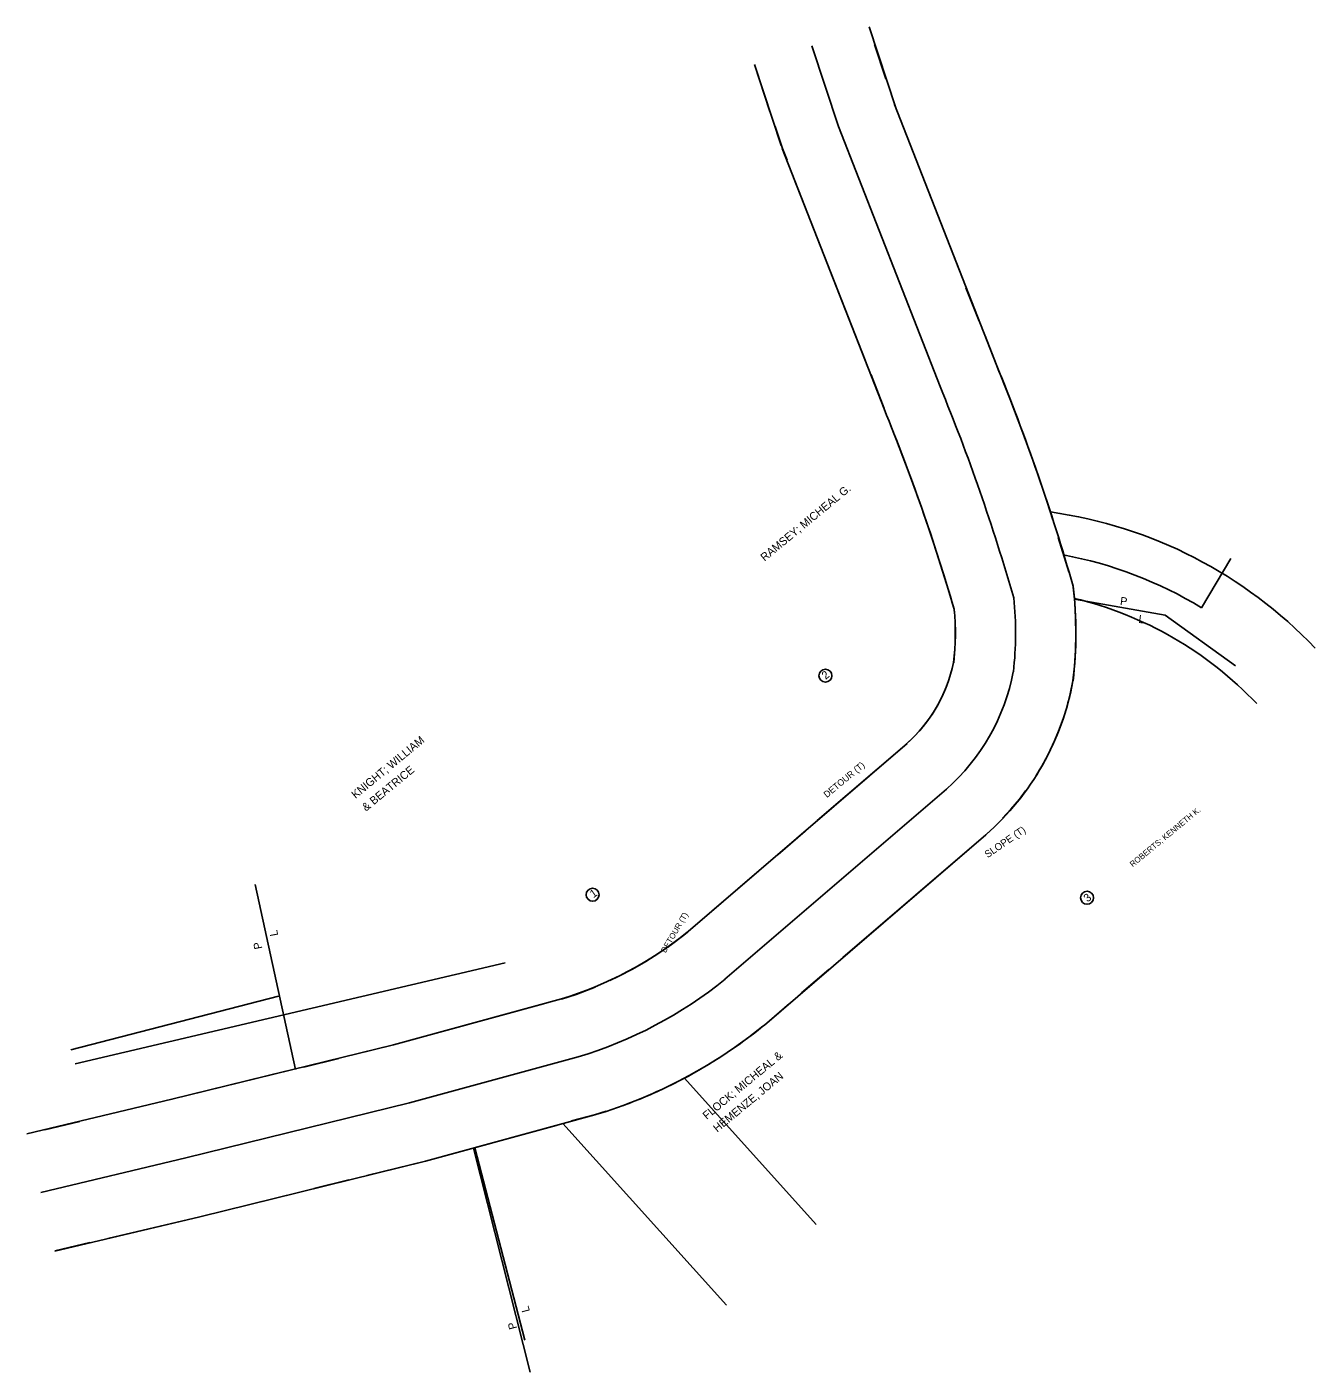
# Model space of a CAD drawing. Extents: x 461210 to 461371, y 202911 to 203079.
import ezdxf

# ---------------------------------------------------------------- set-up
doc = ezdxf.new("R2010")
doc.units = 0
for name, color, linetype in [('Level 1', 7, 'Continuous'), ('Level 3', 7, 'Continuous'), ('Level 4', 7, 'Continuous'), ('Level 5', 7, 'Continuous'), ('Level 6', 7, 'Continuous'), ('Level 7', 7, 'Continuous')]:
    doc.layers.add(name, color=color, linetype=linetype)

msp = doc.modelspace()

# ---------------------------------------------------------------- linework, layer by layer
at = {"layer": 'Level 1'}
for p, q in [((461315.46, 203078.78), (461318.78, 203068.68)), ((461304.44, 203063.97), (461301.12, 203074.08)), ((461318.64, 203069.08), (461331.33, 203036.64)), ((461317.31, 203031.05), (461304.59, 203063.58)), ((461292.52, 202965.5), (461320.19, 202989.26)), ((461330.05, 202977.84), (461302.35, 202954.05)), ((461256.01, 202951.61), (461276.99, 202957.33)), ((461228.3, 202944.8), (461256.01, 202951.61)), ((461210.16, 202940.49), (461228.3, 202944.8)), ((461281.14, 202942.83), (461259.98, 202937.05)), ((461259.98, 202937.05), (461231.79, 202930.12)), ((461231.79, 202930.12), (461213.65, 202925.81))]:
    msp.add_line(p, q, dxfattribs=at)
for points in [[(461316.14, 203076.58), (461317.54, 203072.31)], [(461303.05, 203068.22), (461301.12, 203074.08)], [(461318.2, 203070.44), (461318.78, 203068.68), (461318.64, 203069.08), (461326.74, 203048.36)], [(461305.2, 203062.12), (461304.62, 203063.59), (461304.48, 203063.98), (461303.7, 203066.35)], [(461314.94, 203037.13), (461306, 203059.95)], [(461327.55, 203046.2), (461329.19, 203042.02)], [(461329.94, 203040.18), (461331.33, 203036.64), (461331.33, 203036.64), (461333.04, 203032.37), (461334.68, 203028.07), (461336.24, 203023.74), (461337.72, 203019.38), (461338.43, 203017.19)], [(461317.33, 203031.11), (461315.7, 203035.3)], [(461326.1, 203005.78), (461326.08, 203006.02), (461326.08, 203006.02), (461324.79, 203010.3), (461323.43, 203014.55), (461321.99, 203018.78), (461320.47, 203022.98), (461318.88, 203027.16), (461318.16, 203028.95)], [(461339.1, 203014.99), (461340.4, 203010.68)], [(461340.97, 203008.79), (461341.15, 203006.9), (461341.26, 203004.91), (461341.29, 203002.91), (461341.25, 203000.9), (461341.12, 202998.91), (461340.93, 202997.07), (461340.6, 202995.47), (461340.19, 202993.88), (461339.7, 202992.32), (461339.14, 202990.78), (461338.5, 202989.27), (461337.79, 202987.79), (461337.01, 202986.35), (461336.34, 202985.24)], [(461326.04, 202999.31), (461326.05, 202999.35), (461326.18, 203001.02), (461326.24, 203002.7), (461326.23, 203003.8)], [(461308.94, 202979.61), (461320.19, 202989.26), (461320.12, 202989.2), (461321.01, 202990.04), (461321.83, 202990.93), (461322.6, 202991.87), (461323.31, 202992.86), (461323.95, 202993.89), (461324.51, 202994.97), (461325.01, 202996.08), (461325.39, 202997.09)], [(461335.01, 202983.35), (461334.23, 202982.3), (461333.18, 202981.04), (461332.14, 202979.9)], [(461304.06, 202975.36), (461307.47, 202978.29)], [(461330.76, 202978.49), (461330.05, 202977.84), (461312.18, 202962.5)], [(461283.02, 202959.64), (461284.15, 202960.17), (461285.86, 202961.06), (461287.53, 202962.02), (461289.15, 202963.05), (461290.74, 202964.15), (461292.27, 202965.31), (461292.69, 202965.65), (461292.52, 202965.5), (461302.28, 202973.88)], [(461310.4, 202961.02), (461306.99, 202958.09)], [(461276.98, 202957.29), (461277, 202957.3), (461278.84, 202957.9), (461280.64, 202958.57), (461281.22, 202958.81)], [(461251.06, 202950.4), (461256.01, 202951.61), (461274.74, 202956.72)], [(461305.51, 202956.77), (461302.35, 202954.05), (461302.17, 202953.91), (461300.42, 202952.55), (461298.62, 202951.25), (461296.78, 202950.02), (461294.89, 202948.85), (461292.97, 202947.75), (461291, 202946.73), (461289, 202945.77), (461286.96, 202944.89), (461284.9, 202944.08), (461284.75, 202944.03)], [(461244.78, 202948.81), (461249.15, 202949.89)], [(461218.71, 202942.52), (461228.3, 202944.8), (461242.53, 202948.3)], [(461282.56, 202943.31), (461281.13, 202942.86), (461278.24, 202942.08)], [(461212.42, 202940.99), (461216.79, 202942.03)], [(461276.34, 202941.52), (461259.98, 202937.05), (461252.64, 202935.25)], [(461250.39, 202934.74), (461246.03, 202933.66)], [(461244.11, 202933.15), (461231.79, 202930.12), (461220.29, 202927.39)], [(461218.03, 202926.89), (461213.66, 202925.85)]]:
    msp.add_lwpolyline(points, dxfattribs=at)
for centre, radius, start, end in [((461086.43, 202936.13), 264.72, 15.9547, 22.3136), ((461086.43, 202936.13), 249.63, 16.2572, 22.3493), ((461291.23, 203003.08), 50.07, 353.1088, 6.6715), ((461291.23, 203003.08), 34.98, 353.8885, 4.8139), ((461307.89, 203003.08), 18.49, 311.3811, 348.391), ((461307.89, 203003.08), 33.58, 311.2837, 349.7), ((461263.54, 203001.74), 46.39, 286.8544, 308.9283), ((461263.54, 203001.74), 61.48, 286.6315, 308.9283)]:
    msp.add_arc(centre, radius, start, end, dxfattribs=at)
at = {"layer": 'Level 3'}
for p, q in [((461341.13, 203007.3), (461352.44, 203005.29)), ((461352.44, 203005.29), (461361.24, 202998.93)), ((461243.73, 202948.53), (461238.72, 202971.64)), ((461269.97, 202961.84), (461216.21, 202949.22)), ((461241.63, 202957.68), (461215.67, 202950.96)), ((461266.15, 202938.74), (461272.39, 202914.69))]:
    msp.add_line(p, q, dxfattribs=at)
at = {"layer": 'Level 5'}
for centre in [(461309.99, 202997.72), (461280.88, 202970.35), (461342.69, 202969.97)]:
    msp.add_circle(centre, 0.81, dxfattribs=at)
at = {"layer": 'Level 6'}
for p, q in [((461311.61, 203066.33), (461308.29, 203076.43)), ((461311.61, 203066.33), (461324.32, 203033.85)), ((461356.98, 203006.21), (461360.68, 203012.37)), ((461297.43, 202959.78), (461325.11, 202983.54)), ((461258, 202944.33), (461279.06, 202950.08)), ((461292.37, 202947.43), (461308.83, 202929.14)), ((461230.04, 202937.46), (461258, 202944.33)), ((461277.18, 202941.75), (461297.62, 202919.05)), ((461211.91, 202933.15), (461230.04, 202937.46)), ((461266, 202938.7), (461273.09, 202910.7))]:
    msp.add_line(p, q, dxfattribs=at)
for centre, radius, start, end in [((461086.43, 202936.13), 257.18, 16.0958, 22.3312), ((461330.3, 202962.33), 56.39, 43.5111, 82.0333), ((461330.3, 202962.33), 51.36, 58.7049, 79.4133), ((461291.23, 203003.08), 42.53, 353.4184, 5.8731), ((461330.3, 202962.33), 46.33, 43.5111, 76.512), ((461307.89, 203003.08), 26.04, 311.3811, 349.2176), ((461263.54, 203001.74), 53.94, 286.726, 308.9283)]:
    msp.add_arc(centre, radius, start, end, dxfattribs=at)

# ---------------------------------------------------------------- texts
at = {"layer": 'Level 3'}
for s, rotation, p in [('P', 353.193, (461346.78, 203006.58)), ('L', 353.193, (461349.08, 203004.32)), ('L', 100.6043, (461241.58, 202965.27)), ('P', 100.6043, (461239.6, 202963.63)), ('L', 104.7361, (461273.05, 202918.32)), ('P', 104.7361, (461271.45, 202916.18))]:
    msp.add_text(s, height=1, rotation=rotation, dxfattribs=at).set_placement(p)
at = {"layer": 'Level 4'}
for s, height, p in [('RAMSEY; MICHEAL G.', 1, (461302.38, 203011.96)), ('KNIGHT; WILLIAM', 1, (461251.25, 202982.3)), ('& BEATRICE', 1, (461252.56, 202980.72)), ('ROBERTS; KENNETH K.', 0.729, (461348.4, 202973.76)), ('FLOCK; MICHEAL &', 1, (461295.15, 202942.2)), ('HEMENZE, JOAN', 1, (461296.46, 202940.62))]:
    msp.add_text(s, height=height, rotation=39.5483, dxfattribs=at).set_placement(p)
at = {"layer": 'Level 5'}
for s, rotation, p in [('2', 39.5483, (461310.02, 202997.19)), ('1', 34.6555, (461280.97, 202969.9)), ('3', 39.5483, (461342.76, 202969.37))]:
    msp.add_text(s, height=1, rotation=rotation, dxfattribs=at).set_placement(p)
at = {"layer": 'Level 7'}
for s, height, rotation, p in [('DETOUR (T)', 0.81, 39.5483, (461310.17, 202982.42)), ('SLOPE (T)', 0.9, 34.6555, (461330.27, 202974.9)), ('DETOUR (T)', 0.729, 59.4749, (461290, 202963.02))]:
    msp.add_text(s, height=height, rotation=rotation, dxfattribs=at).set_placement(p)

doc.saveas('drawing.dxf')
